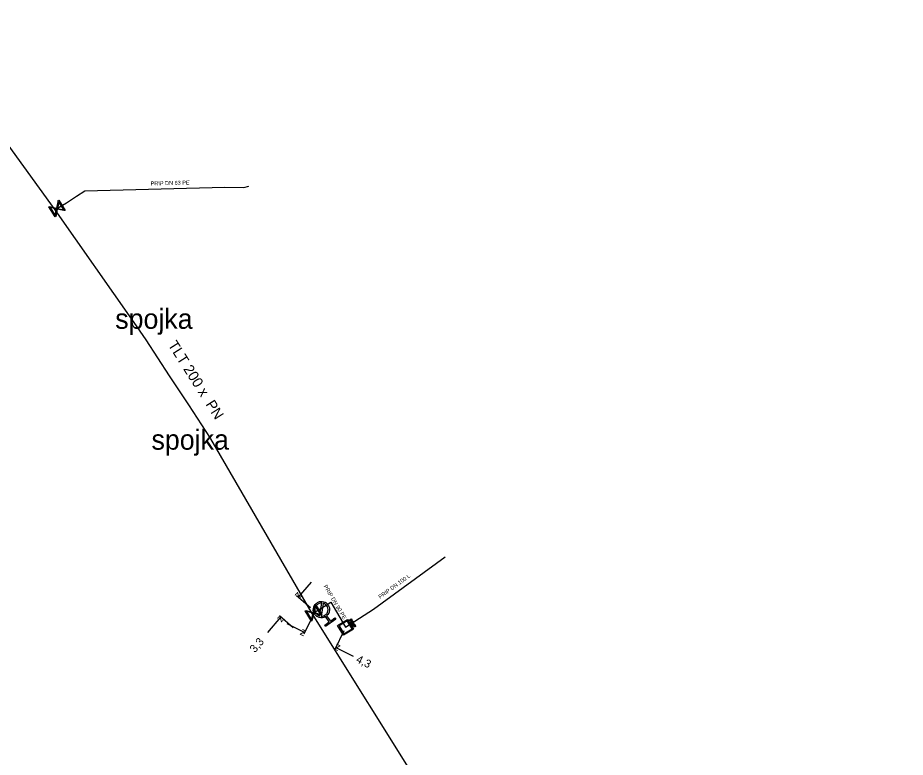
# Model space of a CAD drawing. Extents: x -643544 to -637295, y -1119190 to -1111715.
# Drawn here: x -641181.2 to -641070.3, y -1115640.6 to -1115548.1 of the extents above; entities that cross this region are included whole.
import ezdxf

# ---------------------------------------------------------------- set-up
doc = ezdxf.new("R2010")
doc.units = 0
for name, color, linetype in [('Default', 7, 'Continuous'), ('VP Hydrant', 7, 'Continuous'), ('VP Kótování', 7, 'Continuous'), ('VP Popis nerozlišený', 7, 'Continuous'), ('VP Popis přípojky', 7, 'Continuous'), ('VP Přípojka', 7, 'Continuous'), ('VP Řad', 7, 'Continuous'), ('VP Řad - popis', 7, 'Continuous'), ('VP Šachta', 7, 'Continuous'), ('VP Šoupě', 7, 'Continuous')]:
    doc.layers.add(name, color=color, linetype=linetype)

msp = doc.modelspace()

# ---------------------------------------------------------------- linework, layer by layer
at = {"layer": 'Default'}
for points in [[(-641142.75, -1115622.97), (-641143.06, -1115623.15), (-641143.42, -1115623.09), (-641143.83, -1115623.01), (-641144.07, -1115622.67), (-641144.31, -1115622.34), (-641144.23, -1115621.93), (-641144.16, -1115621.52), (-641143.82, -1115621.28), (-641143.49, -1115621.04), (-641143.08, -1115621.11), (-641142.67, -1115621.18), (-641142.43, -1115621.52), (-641142.19, -1115621.86), (-641142.26, -1115622.27), (-641142.32, -1115622.63), (-641142.6, -1115622.86)], [(-641143.2, -1115621.29), (-641143.48, -1115621.27), (-641143.71, -1115621.44), (-641143.99, -1115621.63), (-641144.05, -1115621.96), (-641144.11, -1115622.29), (-641143.91, -1115622.57), (-641143.74, -1115622.8), (-641143.48, -1115622.88)], [(-641143.3, -1115622.91), (-641143.02, -1115622.93), (-641142.78, -1115622.76), (-641142.5, -1115622.57), (-641142.45, -1115622.24), (-641142.39, -1115621.91), (-641142.58, -1115621.63), (-641142.75, -1115621.39), (-641143.02, -1115621.32)], [(-641139.45, -1115623.39), (-641139.43, -1115623.42), (-641139.43, -1115623.44), (-641139.42, -1115623.46), (-641139.42, -1115623.48), (-641139.42, -1115623.51), (-641139.43, -1115623.53), (-641139.45, -1115623.55), (-641139.47, -1115623.56), (-641139.51, -1115623.58), (-641139.55, -1115623.58), (-641139.59, -1115623.57), (-641139.63, -1115623.5)], [(-641139.59, -1115623.48), (-641139.57, -1115623.52), (-641139.55, -1115623.53), (-641139.52, -1115623.54), (-641139.49, -1115623.52), (-641139.48, -1115623.51), (-641139.47, -1115623.49), (-641139.46, -1115623.47), (-641139.47, -1115623.45), (-641139.47, -1115623.44), (-641139.49, -1115623.41)], [(-641139.49, -1115623.87), (-641139.47, -1115623.84), (-641139.46, -1115623.82), (-641139.46, -1115623.8), (-641139.46, -1115623.78), (-641139.46, -1115623.77), (-641139.46, -1115623.76), (-641139.46, -1115623.75), (-641139.47, -1115623.74)], [(-641139.27, -1115623.68), (-641139.25, -1115623.72), (-641139.24, -1115623.75), (-641139.24, -1115623.78), (-641139.25, -1115623.8), (-641139.26, -1115623.83), (-641139.29, -1115623.84), (-641139.32, -1115623.86), (-641139.36, -1115623.85), (-641139.39, -1115623.85), (-641139.42, -1115623.81), (-641139.42, -1115623.83), (-641139.43, -1115623.84), (-641139.43, -1115623.87), (-641139.45, -1115623.9)], [(-641139.41, -1115623.76), (-641139.4, -1115623.78), (-641139.38, -1115623.8), (-641139.36, -1115623.81), (-641139.35, -1115623.81), (-641139.33, -1115623.81), (-641139.31, -1115623.8), (-641139.29, -1115623.79), (-641139.29, -1115623.76), (-641139.28, -1115623.74), (-641139.31, -1115623.7)], [(-641139.03, -1115624.07), (-641139.02, -1115624.1), (-641139.01, -1115624.12), (-641139, -1115624.15), (-641139, -1115624.17), (-641139, -1115624.19), (-641139.01, -1115624.21), (-641139.03, -1115624.23), (-641139.05, -1115624.25), (-641139.09, -1115624.27), (-641139.13, -1115624.26), (-641139.17, -1115624.25), (-641139.21, -1115624.19)], [(-641139.18, -1115624.17), (-641139.15, -1115624.21), (-641139.13, -1115624.21), (-641139.1, -1115624.22), (-641139.08, -1115624.2), (-641139.06, -1115624.19), (-641139.05, -1115624.18), (-641139.04, -1115624.16), (-641139.05, -1115624.14), (-641139.05, -1115624.13), (-641139.07, -1115624.1)]]:
    msp.add_open_spline(points, degree=3, dxfattribs=at)
at = {"layer": 'VP Hydrant'}
for points in [[(-641143.48, -1115622.88), (-641143.2, -1115621.29)], [(-641143.02, -1115621.32), (-641143.3, -1115622.91)], [(-641142.6, -1115622.86), (-641142.13, -1115623.53), (-641141.56, -1115623.14), (-641141.46, -1115623.29), (-641142.74, -1115624.19), (-641142.84, -1115624.04), (-641142.28, -1115623.64), (-641142.75, -1115622.97)]]:
    msp.add_lwpolyline(points, dxfattribs=at)
at = {"layer": 'VP Kótování'}
for points in [[(-641144.53, -1115618.66), (-641146.16, -1115620.55)], [(-641144.63, -1115621.87), (-641146.35, -1115620.39)], [(-641149.95, -1115624.94), (-641148.32, -1115623.04)], [(-641146.79, -1115624.36), (-641148.5, -1115622.88)], [(-641144.3, -1115622.86), (-641145.45, -1115625.18)], [(-641147.58, -1115623.85), (-641145.34, -1115624.95)], [(-641140.45, -1115624.76), (-641141.59, -1115627.08)], [(-641139.24, -1115627.96), (-641141.48, -1115626.85)]]:
    msp.add_lwpolyline(points, dxfattribs=at)
at = {"layer": 'VP Přípojka'}
for points in [[(-641176.51, -1115572.12), (-641176.29, -1115571.98), (-641175.11, -1115571.25), (-641173.87, -1115570.44), (-641172.83, -1115569.76), (-641155.31, -1115569.29), (-641152.96, -1115569.35), (-641152.3, -1115569.16)], [(-641140.23, -1115624.31), (-641136.76, -1115622.03), (-641127.8, -1115615.5)], [(-641144.39, -1115622.6), (-641144.24, -1115622.51), (-641143.34, -1115621.94), (-641142.08, -1115621.17), (-641140.23, -1115624.31)], [(-641143.25, -1115622.1), (-641143.34, -1115621.94)]]:
    msp.add_lwpolyline(points, dxfattribs=at)
at = {"layer": 'VP Řad'}
for points in [[(-641166.65, -1115586.22), (-641176.51, -1115572.12), (-641186.88, -1115557.84), (-641192.42, -1115548.12)], [(-641157.06, -1115600.76), (-641157.11, -1115600.66), (-641159.8, -1115596.52), (-641162.23, -1115592.86), (-641165.16, -1115588.38), (-641166.65, -1115586.22)], [(-641070.29, -1115767.85), (-641071.15, -1115766.12), (-641089.25, -1115727.27), (-641105.46, -1115689.44), (-641108.97, -1115683), (-641130.28, -1115645.16), (-641144.39, -1115622.6), (-641157.06, -1115600.76)]]:
    msp.add_lwpolyline(points, dxfattribs=at)
at = {"layer": 'VP Šachta'}
for points in [[(-641139.25, -1115624.54), (-641140.48, -1115625.29), (-641141.22, -1115624.09), (-641139.98, -1115623.33), (-641139.25, -1115624.54)], [(-641140.02, -1115623.5), (-641141.05, -1115624.13), (-641140.44, -1115625.13), (-641139.41, -1115624.5), (-641140.02, -1115623.5)], [(-641139.83, -1115623.46), (-641139.52, -1115623.27), (-641139.45, -1115623.39)], [(-641139.63, -1115623.5), (-641139.68, -1115623.42), (-641139.8, -1115623.5), (-641139.83, -1115623.46)], [(-641139.66, -1115623.73), (-641139.35, -1115623.55), (-641139.27, -1115623.68)], [(-641139.47, -1115623.74), (-641139.5, -1115623.69), (-641139.64, -1115623.77), (-641139.66, -1115623.73)], [(-641139.49, -1115623.41), (-641139.53, -1115623.34), (-641139.64, -1115623.4)], [(-641139.64, -1115623.4), (-641139.59, -1115623.48)], [(-641139.31, -1115623.7), (-641139.36, -1115623.61), (-641139.47, -1115623.67)], [(-641139.47, -1115623.67), (-641139.41, -1115623.76)], [(-641139.45, -1115623.9), (-641139.5, -1115624), (-641139.53, -1115623.95), (-641139.49, -1115623.87)], [(-641139.47, -1115624.05), (-641139.17, -1115623.86), (-641139.14, -1115623.9), (-641139.45, -1115624.08), (-641139.47, -1115624.05)], [(-641139.41, -1115624.15), (-641139.1, -1115623.96), (-641139.03, -1115624.07)], [(-641139.21, -1115624.19), (-641139.26, -1115624.11), (-641139.39, -1115624.19), (-641139.41, -1115624.15)], [(-641139.07, -1115624.1), (-641139.12, -1115624.02), (-641139.23, -1115624.09)], [(-641139.23, -1115624.09), (-641139.18, -1115624.17)]]:
    msp.add_lwpolyline(points, dxfattribs=at)
at = {"layer": 'VP Šoupě'}
for points in [[(-641176.07, -1115570.94), (-641175.25, -1115572.2), (-641175.31, -1115572.23), (-641175.43, -1115572.2), (-641176.25, -1115572.03), (-641176.45, -1115572.98), (-641176.51, -1115573.02), (-641177.33, -1115571.76), (-641177.27, -1115571.73), (-641176.32, -1115571.93), (-641176.15, -1115571.11), (-641176.13, -1115570.98), (-641176.07, -1115570.94)], [(-641176.06, -1115571.12), (-641176.24, -1115571.95), (-641175.42, -1115572.12), (-641176.06, -1115571.12)], [(-641176.51, -1115572.84), (-641176.34, -1115572.01), (-641177.16, -1115571.84), (-641176.51, -1115572.84)], [(-641143.98, -1115621.48), (-641143.21, -1115622.76), (-641143.27, -1115622.8), (-641143.39, -1115622.76), (-641144.21, -1115622.56), (-641144.44, -1115623.5), (-641144.5, -1115623.53), (-641145.27, -1115622.25), (-641145.21, -1115622.21), (-641144.27, -1115622.45), (-641144.07, -1115621.64), (-641144.04, -1115621.51), (-641143.98, -1115621.48)], [(-641144.5, -1115623.36), (-641144.29, -1115622.54), (-641145.11, -1115622.33), (-641144.5, -1115623.36)], [(-641143.98, -1115621.66), (-641144.19, -1115622.47), (-641143.37, -1115622.68), (-641143.98, -1115621.66)]]:
    msp.add_lwpolyline(points, dxfattribs=at)

# ---------------------------------------------------------------- texts
at = {"layer": 'VP Kótování'}
for s, rotation, p in [('z', 229.1931, (-641146.21, -1115619.84)), ('z', 49.1931, (-641148.26, -1115623.75)), ('z', 333.7579, (-641146.01, -1115625.18)), ('3,3', 49.1931, (-641151.56, -1115627.56)), ('z', 153.7579, (-641140.81, -1115626.62)), ('4,3', 333.7579, (-641139.01, -1115628.63))]:
    msp.add_text(s, height=1, rotation=rotation, dxfattribs=at).set_placement(p)
at = {"layer": 'VP Popis nerozlišený'}
for p in [(-641169.01, -1115587), (-641164.48, -1115602.11)]:
    msp.add_text('spojka', height=2.5, dxfattribs=at).set_placement(p)
at = {"layer": 'VP Popis přípojky'}
for s, rotation, p in [('PRIP DN 63 PE', 1.5367, (-641164.58, -1115569.09)), ('PRIP DN 100 L', 36.087, (-641135.9, -1115620.77)), ('PRIP DN 90 PE', 300.5835, (-641143, -1115619.18))]:
    msp.add_text(s, height=0.5, rotation=rotation, dxfattribs=at).set_placement(p)
at = {"layer": 'VP Řad - popis'}
msp.add_text('TLT 200 x  PN ', height=1.3, rotation=302.3586, dxfattribs=at).set_placement((-641162.47, -1115589))

doc.saveas('drawing.dxf')
